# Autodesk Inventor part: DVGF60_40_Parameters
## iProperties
Created: 2010-04
Part Number: DVGF60_40_Parameters
Document SubType Name: Modeling
Designer: TB
Density: 1 g/cm^3
Slaglengde: 100.000 mm
Vinkel_Plussport: 0.00 deg
Vinkel_Minusport: 0.00 deg
Forlengelse_rør: 0.000 mm
Author: TB
